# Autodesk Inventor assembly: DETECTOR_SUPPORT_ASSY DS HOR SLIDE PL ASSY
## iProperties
Shininess: 64.0
Length Units: 11272
Angle Units: 11279
Time Units: 11290
Mass Units: 11286
Length Display Precision: 3
Angle Display Precision: 2
Compacted: True
Part Number: DETECTOR_SUPPORT_ASSY DS HOR SLIDE PL ASSY
Document SubType Name: Assembly
Created: 2004-08
Designer: John Blackburn
Manufacturer: Standard
Standards Organization: Custom
Density: 0.0
Volumn: 0.0
Area: 0.0
PropertySet Name: Model Information
Control State: 0
Master: False
Checked Out: False
Author: John Blackburn
